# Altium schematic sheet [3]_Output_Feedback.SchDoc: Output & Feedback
size A4 portrait; DocumentNumber: 3; SheetNumber: 3; SheetTotal: 8
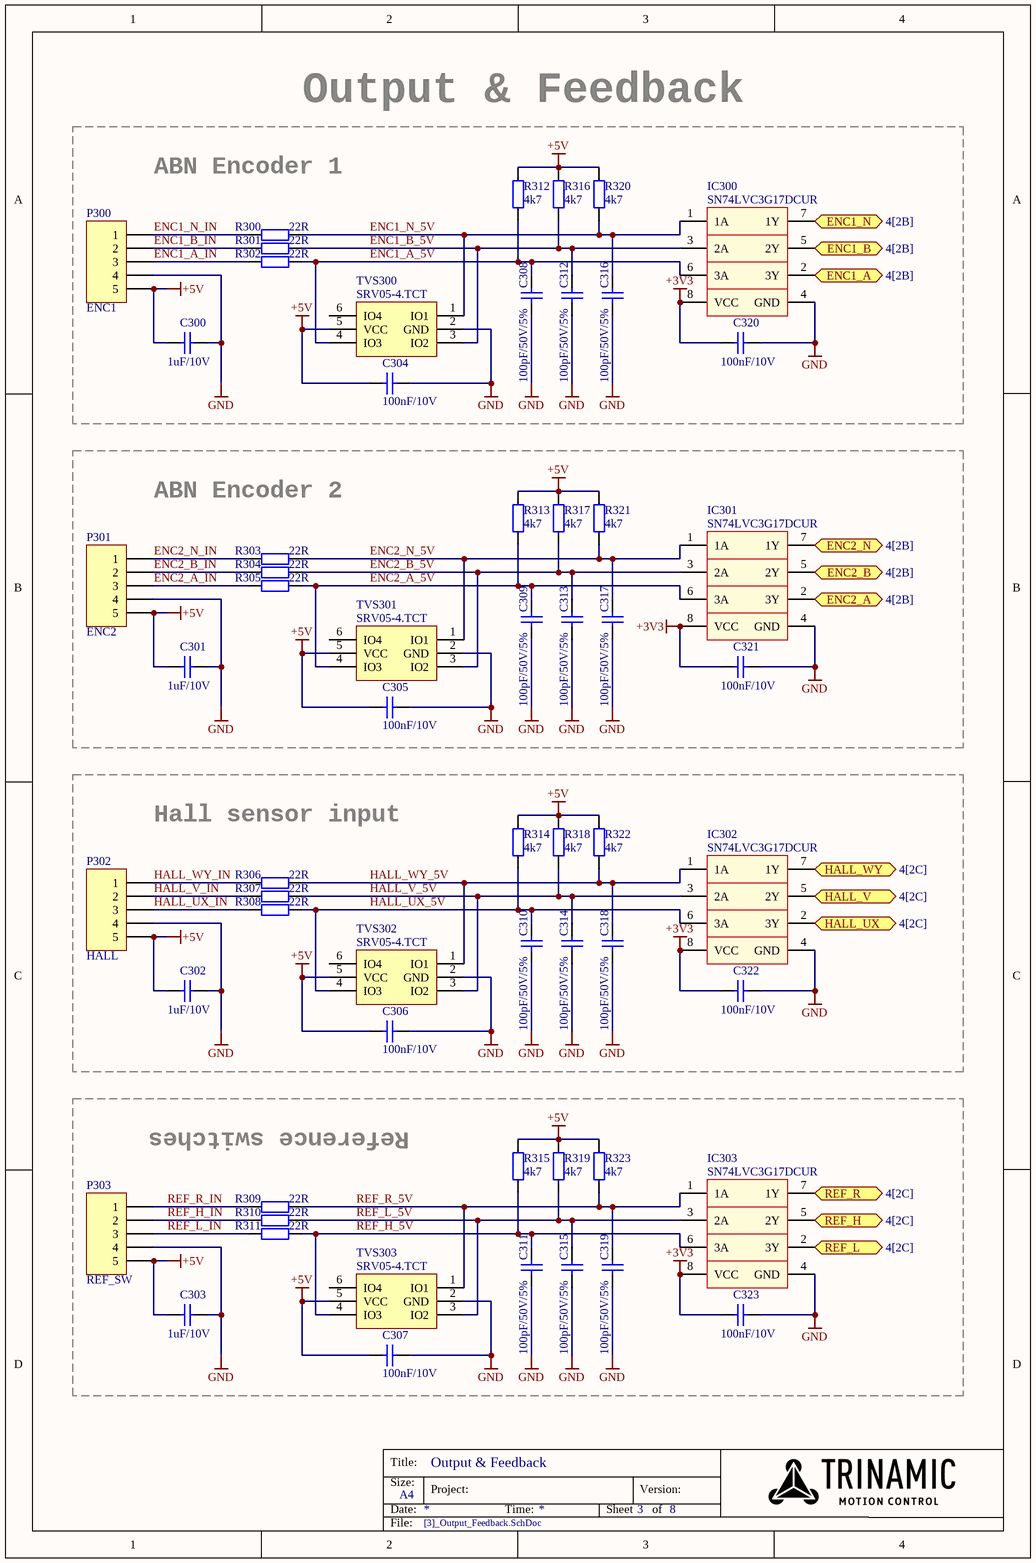
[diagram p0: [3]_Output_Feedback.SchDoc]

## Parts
C300  1uF/10V  [C0603]
C301  1uF/10V  [C0603]
C302  1uF/10V  [C0603]
C303  1uF/10V  [C0603]
C304  100nF/10V  [C0603]
C305  100nF/10V  [C0603]
C306  100nF/10V  [C0603]
C307  100nF/10V  [C0603]
C308  100pF/50V/5%  [C0603]
C309  100pF/50V/5%  [C0603]
C310  100pF/50V/5%  [C0603]
C311  100pF/50V/5%  [C0603]
C312  100pF/50V/5%  [C0603]
C313  100pF/50V/5%  [C0603]
C314  100pF/50V/5%  [C0603]
C315  100pF/50V/5%  [C0603]
C316  100pF/50V/5%  [C0603]
C317  100pF/50V/5%  [C0603]
C318  100pF/50V/5%  [C0603]
C319  100pF/50V/5%  [C0603]
C320  100nF/10V  [C0603]
C321  100nF/10V  [C0603]
C322  100nF/10V  [C0603]
C323  100nF/10V  [C0603]
IC300  SN74LVC3G17DCUR  [TSSOP50P310X90-8L]
IC301  SN74LVC3G17DCUR  [TSSOP50P310X90-8L]
IC302  SN74LVC3G17DCUR  [TSSOP50P310X90-8L]
IC303  SN74LVC3G17DCUR  [TSSOP50P310X90-8L]
P300  ENC1  [TH_HDR_1X5]
P301  ENC2  [TH_HDR_1X5]
P302  HALL  [TH_HDR_1X5]
P303  REF_SW  [TH_HDR_1X5]
R300  22R  [R0603]
R301  22R  [R0603]
R302  22R  [R0603]
R303  22R  [R0603]
R304  22R  [R0603]
R305  22R  [R0603]
R306  22R  [R0603]
R307  22R  [R0603]
R308  22R  [R0603]
R309  22R  [R0603]
R310  22R  [R0603]
R311  22R  [R0603]
R312  4k7  [R0603]
R313  4k7  [R0603]
R314  4k7  [R0603]
R315  4k7  [R0603]
R316  4k7  [R0603]
R317  4k7  [R0603]
R318  4k7  [R0603]
R319  4k7  [R0603]
R320  4k7  [R0603]
R321  4k7  [R0603]
R322  4k7  [R0603]
R323  4k7  [R0603]
TVS300  SRV05-4.TCT  [SOT95P280X145-6N]
TVS301  SRV05-4.TCT  [SOT95P280X145-6N]
TVS302  SRV05-4.TCT  [SOT95P280X145-6N]
TVS303  SRV05-4.TCT  [SOT95P280X145-6N]

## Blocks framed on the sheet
ABN Encoder 1: C300 C304 C308 C312 C316 C320 IC300 P300 R300-R302 R312 R316 R320 TVS300
ABN Encoder 2: C301 C305 C309 C313 C317 C321 IC301 P301 R303-R305 R313 R317 R321 TVS301
Hall sensor input: C302 C306 C310 C314 C318 C322 IC302 P302 R306-R308 R314 R318 R322 TVS302
Reference switches: C303 C307 C311 C315 C319 C323 IC303 P303 R309-R311 R315 R319 R323 TVS303

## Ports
ENC1_A (see 4[2B]), ENC1_B (see 4[2B]), ENC1_N (see 4[2B]), ENC2_A (see 4[2B]), ENC2_B (see 4[2B]), ENC2_N (see 4[2B]), HALL_UX (see 4[2C]), HALL_V (see 4[2C]), HALL_WY (see 4[2C]), REF_H (see 4[2C]), REF_L (see 4[2C]), REF_R (see 4[2C])

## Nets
+3V3: C320.2 C321.2 C322.2 C323.2 IC300.8(VCC) IC301.8(VCC) IC302.8(VCC) IC303.8(VCC)
+5V: C300.2 C301.2 C302.2 C303.2 C304.1 C305.1 C306.1 C307.1 P300.5 P301.5 P302.5 P303.5 R312.2 R313.2 R314.2 R315.2 R316.2 R317.2 R318.2 R319.2 R320.2 R321.2 R322.2 R323.2 TVS300.5(VCC) TVS301.5(VCC) TVS302.5(VCC) TVS303.5(VCC)
GND: C300.1 C301.1 C302.1 C303.1 C304.2 C305.2 C306.2 C307.2 C308.1 C309.1 C310.1 C311.1 C312.1 C313.1 C314.1 C315.1 C316.1 C317.1 C318.1 C319.1 C320.1 C321.1 C322.1 C323.1 IC300.4(GND) IC301.4(GND) IC302.4(GND) IC303.4(GND) P300.4 P301.4 P302.4 P303.4 TVS300.2(GND) TVS301.2(GND) TVS302.2(GND) TVS303.2(GND)
ENC1_A: IC300.2(3Y) ; port ENC1_A
ENC1_A_5V: C308.2 IC300.6(3A) R302.1 R312.1 TVS300.4(IO3)
ENC1_A_IN: P300.3 R302.2
ENC1_B: IC300.5(2Y) ; port ENC1_B
ENC1_B_5V: C312.2 IC300.3(2A) R301.1 R316.1 TVS300.3(IO2)
ENC1_B_IN: P300.2 R301.2
ENC1_N: IC300.7(1Y) ; port ENC1_N
ENC1_N_5V: C316.2 IC300.1(1A) R300.1 R320.1 TVS300.1(IO1)
ENC1_N_IN: P300.1 R300.2
ENC2_A: IC301.2(3Y) ; port ENC2_A
ENC2_A_5V: C309.2 IC301.6(3A) R305.1 R313.1 TVS301.4(IO3)
ENC2_A_IN: P301.3 R305.2
ENC2_B: IC301.5(2Y) ; port ENC2_B
ENC2_B_5V: C313.2 IC301.3(2A) R304.1 R317.1 TVS301.3(IO2)
ENC2_B_IN: P301.2 R304.2
ENC2_N: IC301.7(1Y) ; port ENC2_N
ENC2_N_5V: C317.2 IC301.1(1A) R303.1 R321.1 TVS301.1(IO1)
ENC2_N_IN: P301.1 R303.2
HALL_UX: IC302.2(3Y) ; port HALL_UX
HALL_UX_5V: C310.2 IC302.6(3A) R308.1 R314.1 TVS302.4(IO3)
HALL_UX_IN: P302.3 R308.2
HALL_V: IC302.5(2Y) ; port HALL_V
HALL_V_5V: C314.2 IC302.3(2A) R307.1 R318.1 TVS302.3(IO2)
HALL_V_IN: P302.2 R307.2
HALL_WY: IC302.7(1Y) ; port HALL_WY
HALL_WY_5V: C318.2 IC302.1(1A) R306.1 R322.1 TVS302.1(IO1)
HALL_WY_IN: P302.1 R306.2
REF_H: IC303.5(2Y) ; port REF_H
REF_H_5V: C311.2 IC303.6(3A) R311.1 R315.1 TVS303.4(IO3)
REF_H_IN: P303.2 R310.2
REF_L: IC303.2(3Y) ; port REF_L
REF_L_5V: C315.2 IC303.3(2A) R310.1 R319.1 TVS303.3(IO2)
REF_L_IN: P303.3 R311.2
REF_R: IC303.7(1Y) ; port REF_R
REF_R_5V: C319.2 IC303.1(1A) R309.1 R323.1 TVS303.1(IO1)
REF_R_IN: P303.1 R309.2

Not connected (* = marked no-connect by the designer): TVS300 6(IO4); TVS301 6(IO4); TVS302 6(IO4); TVS303 6(IO4)

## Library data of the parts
C300-C303 = C, 1 µF, 10 V, ± 10%, X5R, MC Series, 0603 [1608 Metric]: SMD Multilayer Ceramic Capacitor, 0603 [1608 Metric], 1 µF, 10 V, ± 10%, X5R, MC Series; MPN: MC0603X105K100CT; Type: MLCC; VoltageRating: 10V; MF: MULTICOMP; Capacitance: 1uF
C304-C307 C320-C323 = C, 0.1 µF, 10 V, ± 10%, X7R, 0603: SMD Multilayer Ceramic Capacitor, 0603 [1608 Metric], 0.1 µF, 10 V, ± 10%, X7R, MC Series; MPN: MC0603B104K100CT; Type: MLCC; VoltageRating: 10V; MF: Multicomp; Capacitance: 100nF
C308-C319 = C, 100 pF, 50 V, ± 5%, C0G / NP0, MC Series, 0603 [1608 Metric]: SMD Multilayer Ceramic Capacitor, 0603 [1608 Metric], 100 pF, 50 V, ± 5%, C0G / NP0, MC Series; MPN: MC0603N101J500CT; Type: MLCC; VoltageRating: 50V; MF: MULTICOMP; Capacitance: 100pF
IC300-IC303 = SN74LVC3G17DCUR: Triple Schmitt-Trigger Buffer, 74LVC3G17, 1.65 V to 5.5 V, VSSOP-8; MF: TEXAS INSTRUMENTS
P300-P303 = Header 5: Header, 5-Pin
R300-R311 = R, 22 ohm, 50 V, 0603 [1608 Metric], 100 mW, ± 1%, MCWR Series: SMD Chip Resistor, Thick Film, 22 ohm, 50 V, 0603 [1608 Metric], 100 mW, ± 1%, MCWR Series; MPN: MCWR06X22R0FTL; VoltageRating: 50V; Temp coefficient: *ppm; PowerRating: 100mW; MF: MULTICOMP
R312-R323 = R, 4.7 kohm, 75 V, 0603 [1608 Metric], 100 mW, ± 1%, WR06 Series: SMD Chip Resistor, 4.7 kohm, 75 V, 0603 [1608 Metric], 100 mW, ± 1%, WR06 Series; MPN: WR06X4701FTL; VoltageRating: 75V; Temp coefficient: *ppm; PowerRating: 100mW; MF: WALSIN
TVS300-TVS303 = ESD, TVS, SRV05-4.TCT: ESD Protection Device, TVS, 17.5 V, SOT-23, 6 Pins, 5 V, 300 W; MF: SEMTECH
